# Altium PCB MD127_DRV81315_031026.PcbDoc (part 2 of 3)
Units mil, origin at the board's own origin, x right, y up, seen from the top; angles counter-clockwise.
Board outline 4400.04 x 2800.87 mil, 2 copper layers (Top Layer, Bottom Layer), stack 64.712 mil thick; 156 components, 62 nets, 376 pads, 751 vias.
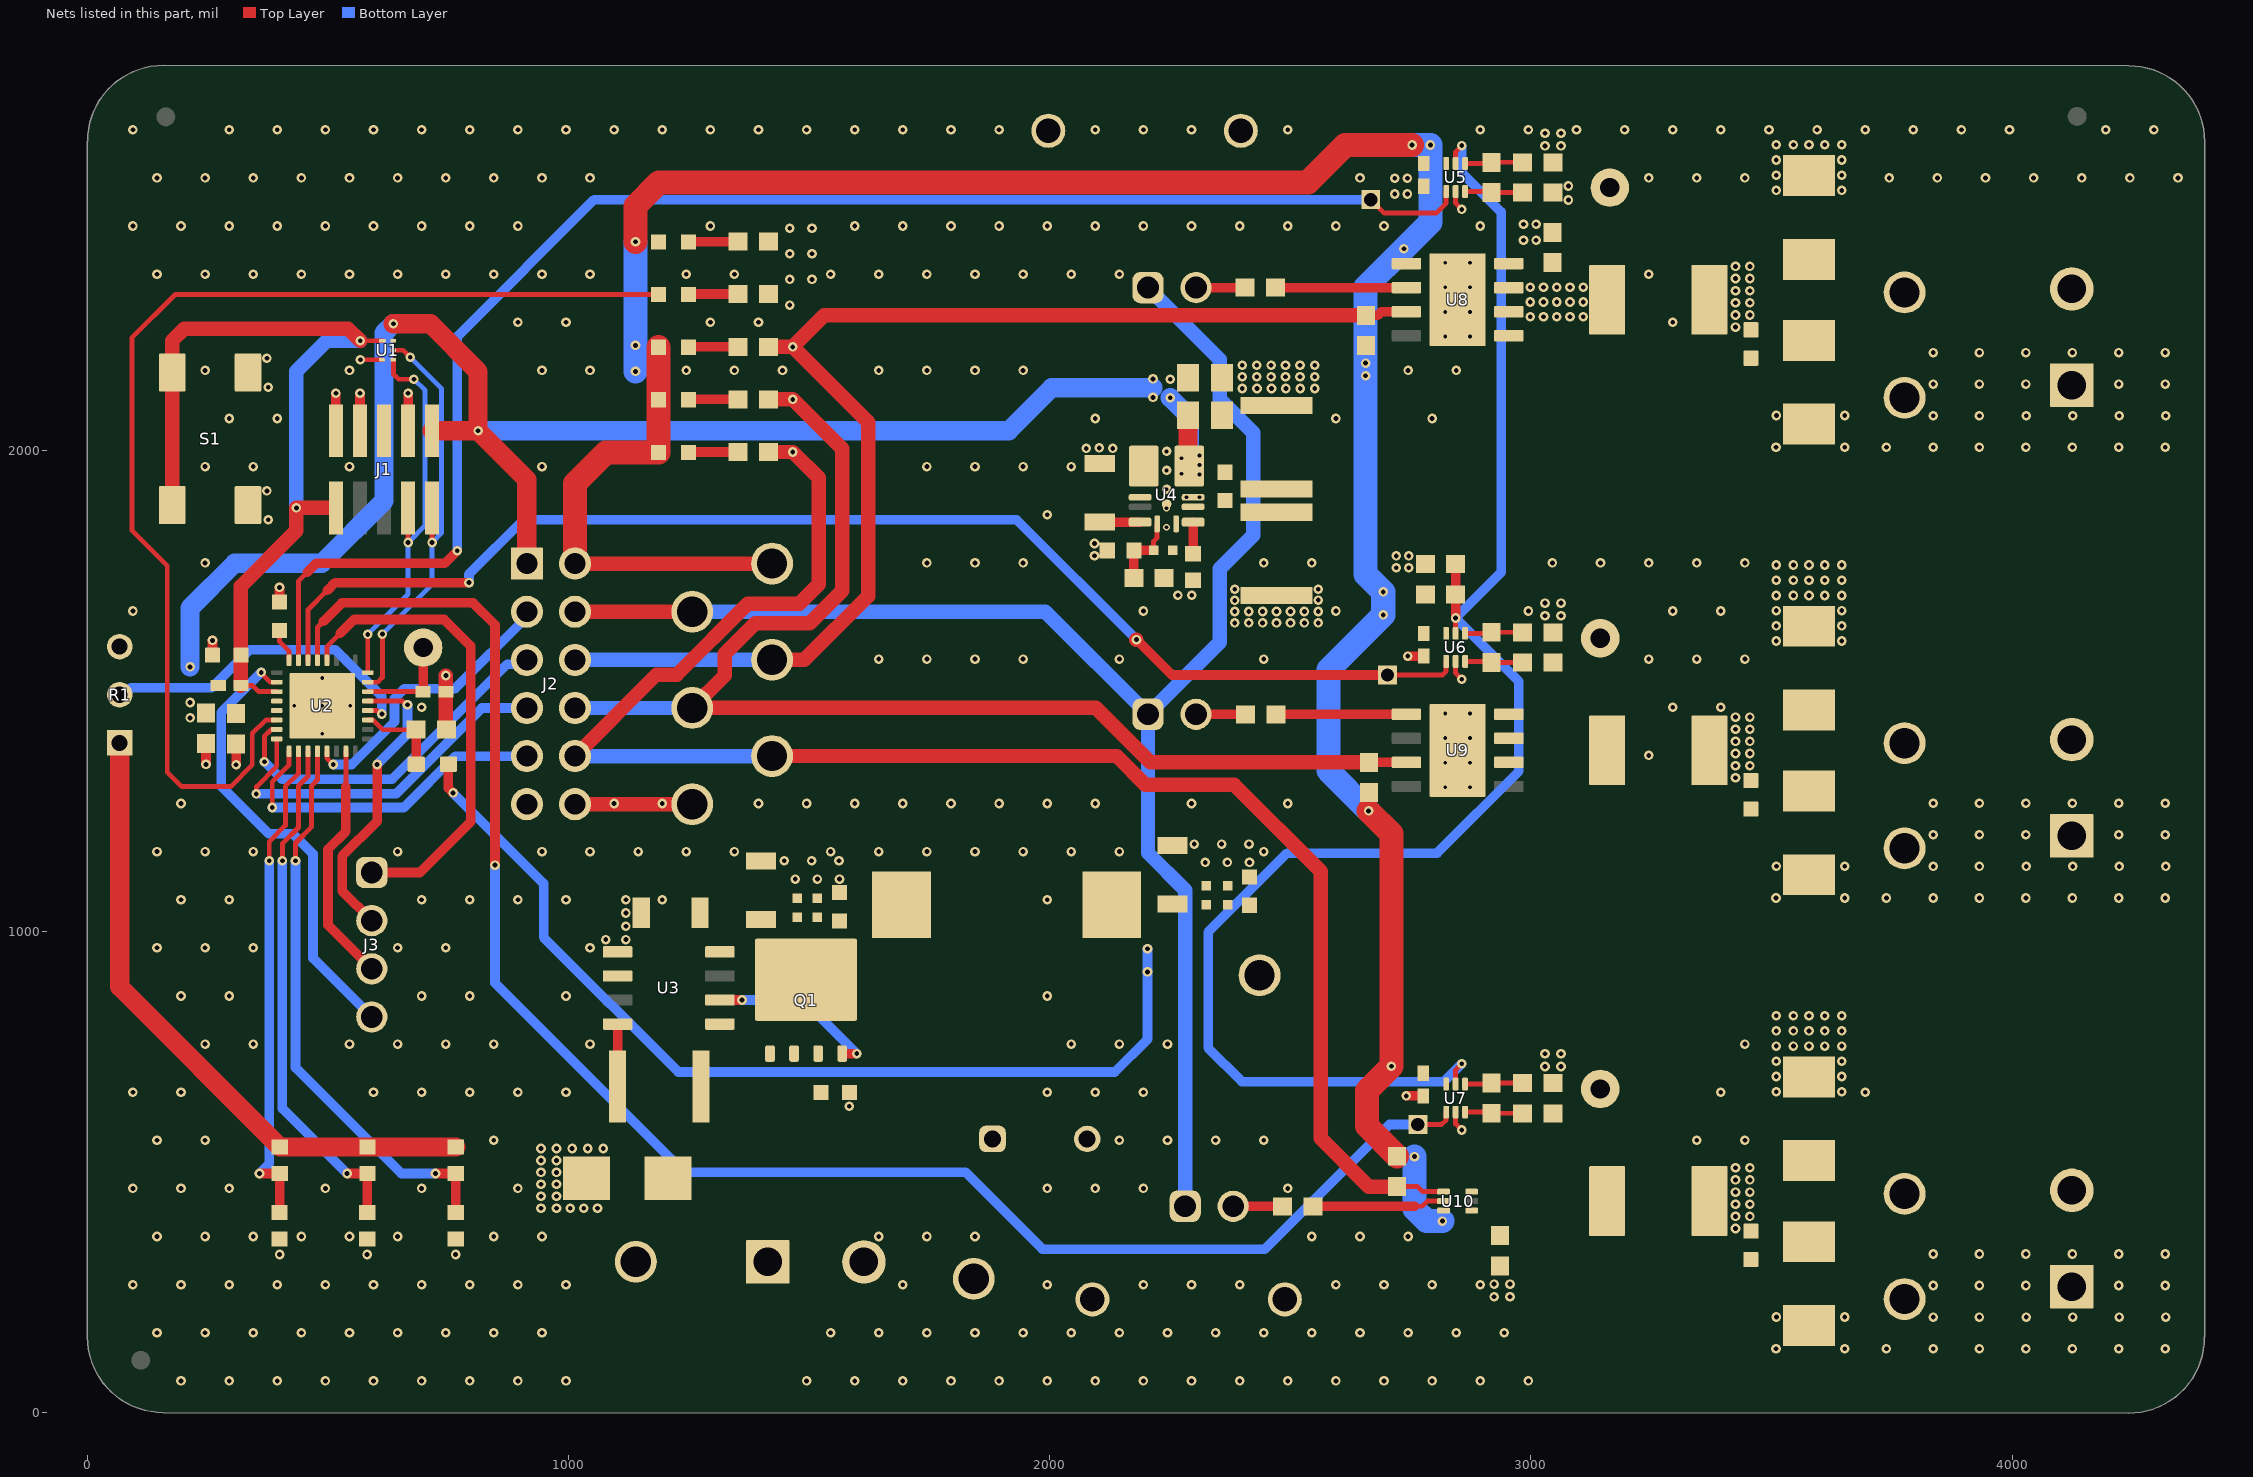
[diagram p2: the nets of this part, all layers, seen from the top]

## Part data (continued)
R1: library part CMP-0001777-2, "Trimming Potentiometer, 50K, 0.5W, TH", Manufacturer=Bourns, Supplier Part Number 1=3352T-503LF-ND
R2 R3: library part CMP-0026935-3, "RES, 47 k, 5%, 0.063 W, AEC-Q200 Grade 0, 0402", Manufacturer=Vishay-Dale, Power_W=63mW, Supplier Part Number 1=541-47KJCT-ND, TempCo="200 ppm/C", Tolerance_%=5%, Value2=0.063W, Value_Code=47k0, ValueDisplayed=47k
R4: library part CMP-0025899-5, "RES, 1.0 k, 5%, 0.1 W, 0603", Manufacturer=Yageo, Power_W=100mW, Supplier Part Number 1=311-1.0KGRCT-ND, TempCo="100 ppm/C", Tolerance_%=5%, Value2=0.1W, Value_Code=1k00, ValueDisplayed=1.0k
R5: library part CMP-0122747-1, "8 kOhms ±0.1% 0.1W, 1/10W Chip Resistor 0603 (1608 Metric) Thin Film", Digikey Part Number=13-RT0603BRE078KLCT-ND, Manufacturer=Yageo, Mouser Part Number=603-RT0603BRE078KL, Operating Temperature Range="-55°C to +155°C", Power_W=100mW, TempCo=50ppm/°C, Tolerance_%=0.1%
R6 R7 R8 R9 R10 R11 R17: library part CMP-0025886-5, "RES, 10 k, 5%, 0.1 W, 0603", Manufacturer=Yageo, Power_W=100mW, Supplier Part Number 1=311-10KGRCT-ND, TempCo="100 ppm/C", Tolerance_%=5%, Value2=0.1W, Value_Code=10k0, ValueDisplayed=10k
R12 R20 R21 R22: library part CMP-0022895-5, "RES, 1.00 k, 1%, 0.1 W, 0603", Manufacturer=Yageo, Power_W=100mW, Supplier Part Number 1=311-1.00KHRCT-ND, TempCo="100 ppm/C", Tolerance_%=1%, Value2=0.1W, Value_Code=1k00, ValueDisplayed=1.00k
R13 R14 R15 R16: library part CMP-0025912-5, "RES, 330, 5%, 0.1 W, 0603", Manufacturer=Yageo, Power_W=100mW, Supplier Part Number 1=311-330GRCT-ND, TempCo="100 ppm/C", Tolerance_%=5%, Value2=0.1W, Value_Code=330R, ValueDisplayed=330
R18: library part CMP-0022933-5, "RES, 23.2 k, 1%, 0.1 W, 0603", Manufacturer=Yageo, Power_W=100mW, Supplier Part Number 1=311-23.2KHRCT-ND, TempCo="100 ppm/C", Tolerance_%=1%, Value2=0.1W, Value_Code=23k2, ValueDisplayed=23.2k
R19: library part CMP-0025886-3, "RES, 10 k, 5%, 0.1 W, 0603", Manufacturer=Yageo, Power_W=100mW, Supplier Part Number 1=311-10KGRCT-ND, TempCo="100 ppm/C", Tolerance_%=5%, Value2=0.1W, Value_Code=10k0, ValueDisplayed=10k
R23 R24 R25: library part CMP-0023155-5, "RES, 4.99 k, 1%, 0.1 W, 0603", Manufacturer=Yageo, Power_W=100mW, Supplier Part Number 1=311-4.99KHRCT-ND, TempCo="100 ppm/C", Tolerance_%=1%, Value2=0.1W, Value_Code=4k99, ValueDisplayed=4.99k
R26 R27: library part CMP-0022902-5, "RES, 200, 1%, 0.1 W, 0603", Manufacturer=Yageo, Power_W=100mW, Supplier Part Number 1=311-200HRCT-ND, TempCo="100 ppm/C", Tolerance_%=1%, Value2=0.1W, Value_Code=200R, ValueDisplayed=200
R28 R29 R31 R32 R33 R34: library part CMP-0025874-4, "RES, 0, 5%, 0.1 W, AEC-Q200 Grade 0, 0603", Manufacturer=Panasonic, Power_W=100mW, Supplier Part Number 1=P0.0GCT-ND, TempCo="600 ppm/C", Tolerance_%=5%, Value2=0.1W, Value_Code=0000, ValueDisplayed=0
R30 R35: library part CMP-0022735-5, "RES, 100 k, 1%, 0.1 W, 0603", Manufacturer=Yageo, Power_W=100mW, Supplier Part Number 1=311-100KHRCT-ND, TempCo="100 ppm/C", Tolerance_%=1%, Value2=0.1W, Value_Code=100k
R36 R37 R38: library part CMP-0088493-1, "10 mOhms ±0.5% 2W Chip Resistor 2512 (6432 Metric) Automotive AEC-Q200, Current Sense, Moisture Resistant Metal Film", Digikey Part Number=273-PCS2512DR0100ETCT-ND, Manufacturer=Ohmite, Mouser Part Number=588-PCS2512DR0100ET, Operating Temperature Range="-55°C to +170°C", Power_W=2W, TempCo=50ppm/°C, Tolerance_%=0%
S1: library part CMP-0097347-1, "Tactile Switch SPST-NO Top Actuated Surface Mount", Coil Resistance_ohm=100mΩ, Contact Current Rating=50mA, Digikey Part Number=732-7022-1-ND, Manufacturer="Wurth Electronics", Mouser Part Number=710-430481025816, Operating Force=160gf, Operating Temperature Range="-40°C to +85°C"
SH1 SH2: library part CMP-0075110-1, "1mm Uninsulated Shorting Plug, 10.16mm spacing, TH", Manufacturer=Harwin, PartNumber=D3082-05, Supplier Part Number 1=952-1873-ND
SH1-J2 SH2-J2 SH3-J2 SH4-J2 SH5-J2 SH6-J2 SH-J5 SH-J6 SH-J7: library part CMP-0003761-2, "Shunt, 2.54mm, Gold, Black", Manufacturer="Wurth Elektronik", Supplier Part Number 1=732-2678-ND
TP1 TP11 TP12 TP13: library part CMP-0055139-2, "Test Point, Miniature, White, TH", Color=White, Manufacturer="Keystone Electronics", Supplier Part Number 1=36-5002-ND
TP2: library part CMP-0055150-1, "Test Point, Multipurpose, Orange, TH", Color=Orange, Manufacturer=Keystone, Supplier Part Number 1=36-5013-ND
TP3 TP4 TP5 TP6 TP14 TP16 TP18: library part CMP-0055149-2, "Test Point, Multipurpose, White, TH", Color=White, Manufacturer="Keystone Electronics", Supplier Part Number 1=36-5012-ND
TP7 TP9: library part CMP-0055148-2, "Test Point, Multipurpose, Black, TH", Color=Black, Manufacturer="Keystone Electronics", Supplier Part Number 1=36-5011-ND
TP8 TP10 TP15 TP17 TP19: library part CMP-0055147-2, "Test Point, Multipurpose, Red, TH", Color=Red, Manufacturer="Keystone Electronics", Supplier Part Number 1=36-5010-ND
U1: library part CMP-0043115-2, "ESD-Protection Array for High-Speed Data Interfaces, 4 Channels, -40 to +85 degC, 6-pin SON (DRY), Green (RoHS & no Sb/Br)", Breakdown Voltage(Min)(V)=6, IO Capacitance(Typ)(pF)=1.6, IO Leakage Current(nA)=1, Manufacturer="Texas Instruments"
U2: library part CMP-0093963-1, "Mixed-Signal Microcontrollers with CAN-FD Interface, VQFN32", Frequency_Fixed=80MHz, Manufacturer="Texas Instruments", Max Supply Voltage=3.6V, Min Supply Voltage=1.62V, Operating Temperature Range="-40°C to +125°C"
U3: library part CMP-0125797-1, Manufacturer="Texas Instruments", Operating Temperature Range=to, Part Number=LM74700D-Q1
U4: library part CMP-0094617-1, "3-V to 65-V Input, 1-V to 13-V Output, 600-mA Synchronous Buck Converter Power Module in a HotRod QFN Package", Manufacturer="Texas Instruments", Max Supply Voltage=65V, Min Supply Voltage=3.6V, Nominal Supply Current=17-18uA, Operating Temperature Range="-40°C to +125°C", Output Voltage=1-13V, Switching Frequency=200-2200kHz
U5 U6 U7: library part CMP-0085242-1, "Bidirectional, Precision Low- and High-Side Voltage Output, Current-Sense Amplifier, DRL0006A (SOT-5X3-6)", Alternate Manufacturer="Texas Instruments", Alternate PartNumber=INA185A2IDRLT
U8: library part CMP-0127675-1, "Protected Low-Side Switch, HSOIC8", Manufacturer="Texas Instruments", Max Supply Voltage=5.5V, Min Supply Voltage=3V, Nominal Supply Current=40uA, Operating Temperature Range="-40°C to +150°C"
U9: library part CMP-0127704-1, "Protected Low-Side Switch, HSOIC8", Manufacturer="Texas Instruments", Max Supply Voltage=5.5V, Min Supply Voltage=3V, Nominal Supply Current=40uA, Operating Temperature Range="-40°C to +150°C"
U10: library part CMP-0127676-1, "Protected Low-Side Switch, SOT563", Manufacturer="Texas Instruments", Max Supply Voltage=5.5V, Min Supply Voltage=3V, Nominal Supply Current=40uA, Operating Temperature Range="-40°C to +150°C"
ZZ1: library part CMP-0003616-3
ZZ2: library part CMP-0077236-1
ZZ3: library part CMP-0077237-1
ZZ4: library part CMP-0077238-1

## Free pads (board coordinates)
  rect 39.37x39.37 hole 27.56: 7(2667,2521) 7(2702,1533) 7(2765,599)

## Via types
v1: diameter 20, hole 10, Top Layer to Bottom Layer, tented both sides, 718 vias
v2: diameter 19.68, hole 7.87, Top Layer to Bottom Layer, tented both sides, 29 vias
v3: diameter 14, hole 8, Top Layer to Bottom Layer, tented both sides, 4 vias

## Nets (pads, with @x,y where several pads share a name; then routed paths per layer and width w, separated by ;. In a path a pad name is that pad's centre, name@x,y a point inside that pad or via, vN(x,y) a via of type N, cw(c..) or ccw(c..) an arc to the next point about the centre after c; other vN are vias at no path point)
3V3: C24.2 C25.2 C26.2 D1.2 D3.2 D4.2 D5.2 J2.2 R23.1 R24.1 R25.1 R27.2 TP2.1 U5.6 U6.6 U7.6 U8.1 U10.3 | length 5541.6
  Top Layer w30: J2.2@1013.3,1764.56 1422.78,1764.56 TP2.1@1422.91,1764.69
  Top Layer w50: J2.2@1013.3,1764.56 1013.3,1931.3 1077.77,1995.77 D5.2@1186.51,1995.77 D4.2@1186.51,2105 D3.2@1186.51,2214.23 ; v1(1139,2433.35) 1139,2507.82 1188.18,2557 2536.33,2557 2613.97,2634.63 v1(2753,2634.63) ; v1(2662.59,1250.67) 2710,1203.26 v1(2710,720) 2659,669 2659,595.53 R25.1@2721.62,532.91
  Bottom Layer w50: v1(1139,2164) v1(1139,2218) v1(1139,2433.35) ; v1(2662.59,1250.67) 2579,1334.26 2579,1544 v1(2693,1658) v1(2693,1705.81) 2656.37,1742.44 v1(2656.37,2155) v1(2656.37,2181.25) 2656.37,2339.37 v1(2736,2419) 2791,2474 v1(2791,2634.63) v1(2753,2634.63) ; v1(2757.87,532.28) 2757.87,423.64 2783.27,398.23 v1(2815.98,398.23)
A0_3_ADC0_AUX: J3.1 U2.28 | length 987.9
  Top Layer w10: U2.28@497.84,1563.49 497.84,1592.09 525.72,1619.96
  Top Layer w20: 525.72,1619.96 554.21,1648.46 741.54,1648.46 796.3,1593.7 796.3,1227.82 691,1122.52 J3.1@591,1122.52
A1_2_ADC1_AUX: J3.2 U2.21 | length 616.1
  Top Layer w10: U2.21@582.49,1478.84 654.74,1478.84 662.44,1471.15 v1(665.14,1471.15)
  Top Layer w20: J3.2@591,1022.52 529.57,1083.95 529.57,1156.57 602,1229 v1(602,1347)
  Bottom Layer w20: v1(602,1347) 665.14,1410.14 v1(665.14,1471.15)
BSL_INVOKE: R3.2 TP1.1 U2.22 | length 206.7
  Top Layer w10: U2.22@582.49,1498.53 R3.2@697.75,1498.53
  Top Layer w20: R3.2@697.75,1498.53 TP1.1@697.75,1590
BUCK_3V3: C3.1 C4.1 C13.1 C14.1 C16.2 J1.1 J2.1 R1.1 R2.2 R6.1 R7.1 R8.1 R18.2 R19.2 U1.6 U2.4 U4.4 | length 4795.6
  Top Layer w40: R1.1@67,1392.09 67,885.06 R6.1@399.78,552.28 R7.1@581.76,552.28 R8.1@765.55,552.28 ; v1(635.81,2263) 713,2263 812,2164 v1(812,2040.6) ; J1.1@716.46,2040.6 v1(812,2040.6) ; J2.1@913.3,1764.56 913.3,1939.3 v1(812,2040.6) ; C14.1@2287.28,2072.53 2287.28,1970.04 U4.4@2290,1967.32
  Bottom Layer w40: v1(213.44,1550) 213.44,1672.44 306.22,1765.22 487.1,1765.22 616.46,1894.57 616.46,2243.64 v1(635.81,2263) ; v1(812,2040.6) 1914.6,2040.6 2004,2130 2214.62,2130 ; v1(2250.54,2109.14) 2290,2069.68 2290,1967.32
  other v1: 213.44,1444 213.44,1475.91 2266.18,1698.64 2295.07,1698.64 2214.62,2110.02 2214.62,2148.42 2250.54,2147.77
  other v2: 2310.87,1949.61 2273.46,1951.18 2310.87,1969.29 2273.46,1983.46 2310.87,1988.98
DEV_ID1: R6.2 R9.1 U2.10 | length 1034.2
  Top Layer w10: v1(378.01,1147.18) 378.01,1187.01 411.55,1220.55 411.55,1301.79 438.79,1329.02 U2.10@438.79,1374.51
  Top Layer w20: v1(357.76,497.16) R6.2@399.78,497.16 399.78,416.28 R9.1@399.48,415.98
  Bottom Layer w20: v1(357.76,497.16) 378.01,517.42 v1(378.01,1147.18)
DEV_ID2: R7.2 R10.1 U2.11 | length 1078.5
  Top Layer w10: v1(405.13,1147.18) 405.13,1182.67 438.67,1216.21 438.67,1302.52 458.47,1322.32 U2.11@458.47,1374.51
  Top Layer w20: v1(539.73,497.16) R7.2@581.76,497.16 581.76,416.14 R10.1@581.6,415.98
  Bottom Layer w20: v1(405.13,1147.18) 405.13,631.77 v1(539.73,497.16)
DEV_ID3: R8.2 R11.1 U2.12 | length 1181.8
  Top Layer w10: v1(432.46,1147.18) 432.46,1183.97 466,1217.51 466,1303 478.16,1315.16 U2.12@478.16,1374.51
  Top Layer w20: v1(723.52,497.16) R8.2@765.55,497.16 R11.1@765.55,415.98
  Bottom Layer w20: v1(432.46,1147.18) 432.46,717.03 652.33,497.16 v1(723.52,497.16)
GND: C1.1 C2.2 C3.2 C4.2 C5.1 C6.1 C7.1 C8.1 C9.1 C11.1 C12.2 C13.2 C14.2 C15.1 C17.1 C18.1 C19.1 C20.1 C21.1 C22.1 C23.1 C24.1 C25.1 C26.1 C30.1 C31.1 C32.1 D6.2 D7.1 D8.1 D9.1 J1.3 J1.5 J1.7 J1.9 J2.11 J2.12 J4.2 R1.3 R3.1 R4.1 R9.2 R10.2 R11.2 R12.1 R13.1 R17.1 R26.1 R28.1 R30.1 R31.1 R33.1 R35.1 R36.1 R37.1 R38.1 S1.3 S1.4 SH1.1 SH1.2 SH2.1 SH2.2 TP7.1 TP9.1 U1.3 U2.5 U2.33 U3.1 U4.10 U4.11 U5.2 U6.2 U7.2 U8.9 | length 978.8
  Top Layer w10: v1(567.33,2188.31) U1.3@612.19,2188.31 ; U7.2@2843.37,624.64 2843.37,600.18 v1(2856,587.55) ; U6.2@2843.37,1561.27 2843.37,1536.81 v1(2856,1524.18) ; U5.2@2843.37,2537.91 2843.37,2513.45 v1(2856,2500.82)
  Top Layer w20: v1(246.51,1347.4) C3.2@246.51,1390.71 ; C2.2@260.01,1574.33 v1(260.01,1605) ; v1(309,1346.7) C4.2@309,1390.01 ; C1.1@399.1,1684.52 v1(399.1,1715.19) ; J1.9@516.46,2040.6 v1(516.46,2118.55) ; J1.7@566.45,2040.6 v1(566.45,2118.55) ; J1.3@666.45,2040.6 v1(666.45,2118.55) ; v1(2741,658.3) C26.1@2775.95,658.3 ; v1(2744,1572.3) C25.1@2777.36,1572.3
  Top Layer w30: v1(744.99,1531.99) R3.1@744.99,1498.53 744.99,1420.81 R4.1@746.33,1419.47 ; J2.12@1013.3,1264.56 1256.9,1264.56 TP7.1@1257.04,1264.69
  other v1: 194.61,66.09 294.61,66.09 394.61,66.09 494.61,66.09 594.61,66.09 694.61,66.09 794.61,66.09 894.61,66.09 994.61,66.09 1494.61,66.09 1594.61,66.09 1694.61,66.09 1794.61,66.09 1894.61,66.09 1994.61,66.09 2094.61,66.09 2194.61,66.09 2294.61,66.09 2394.61,66.09 2494.61,66.09 2594.61,66.09 2694.61,66.09 2794.61,66.09 2894.61,66.09 2994.61,66.09 144.61,166.09 244.61,166.09 344.61,166.09 444.61,166.09 544.61,166.09 644.61,166.09 744.61,166.09 844.61,166.09 944.61,166.09 1544.61,166.09 1644.61,166.09 1744.61,166.09 1844.61,166.09 1944.61,166.09 2044.61,166.09 2144.61,166.09 2244.61,166.09 2344.61,166.09 2444.61,166.09 2544.61,166.09 2644.61,166.09 2744.61,166.09 2844.61,166.09 2944.61,166.09 2923.33,241 2956.35,241 94.61,266.09 194.61,266.09 294.61,266.09 394.61,266.09 494.61,266.09 594.61,266.09 694.61,266.09 794.61,266.09 894.61,266.09 994.61,266.09 1694.61,266.09 1994.61,266.09 2194.61,266.09 2294.61,266.09 2394.61,266.09 2594.61,266.09 2694.61,266.09 2794.61,266.09 2894.61,266.09 2923.33,267.26 2956.35,267.26 399.4,328.75 581.38,328.75 765.17,328.75 144.61,366.09 244.61,366.09 344.61,366.09 444.61,366.09 544.61,366.09 644.61,366.09 844.61,366.09 944.61,366.09 1644.61,366.09 1744.61,366.09 1844.61,366.09 2544.61,366.09 2644.61,366.09 2744.61,366.09 3425,382.75 3425,408 3455,408 942.67,425 975,425 1003.33,425 1031.67,425 1060,425 3425,433.25 3455,433.25 942.67,449.8 975,449.8 3425,458.5 3455,458.5 94.61,466.09 194.61,466.09 294.61,466.09 494.61,466.09 694.61,466.09 894.61,466.09 1994.61,466.09 2094.61,466.09 2194.61,466.09 2494.61,466.09 942.67,474.6 975,474.6 3425,483.75 3455,483.75 942.67,499.4 975,499.4 3425,509 3455,509 942.67,524.2 975,524.2 942.67,549 975,549 1007.33,549 1039.67,549 1072,549 144.61,566.09 244.61,566.09 844.61,566.09 2144.61,566.09 2244.61,566.09 2344.61,566.09 2444.61,566.09 3344.61,566.09 3444.61,566.09 1583.24,636.99 94.61,666.09 194.61,666.09 594.61,666.09 694.61,666.09 794.61,666.09 894.61,666.09 994.61,666.09 1994.61,666.09 2094.61,666.09 2194.61,666.09 3394.61,666.09 3694.61,666.09 3509.77,667 3646,667 3509.77,698.6 3646,698.6 3029.3,719.52 3062.32,719.52 3509.77,730.2 3646,730.2 3029.3,745.78 3062.32,745.78 3509.77,761.8 3545.33,761.8 3577.88,761.8 3610.44,761.8 3646,761.8 244.61,766.09 344.61,766.09 544.61,766.09 644.61,766.09 744.61,766.09 844.61,766.09 1044.61,766.09 2044.61,766.09 2144.61,766.09 2244.61,766.09 3444.61,766.09 3509.77,793.4 3545.33,793.4 3577.88,793.4 3610.44,793.4 3646,793.4 3509.77,825 3545.33,825 3577.88,825 3610.44,825 3646,825 194.61,866.09 294.61,866.09 694.61,866.09 794.61,866.09 994.61,866.09 1994.61,866.09 144.61,966.09 244.61,966.09 344.61,966.09 644.61,966.09 744.61,966.09 1044.61,966.09 1077.4,983.26 1119,983.26 1119,1010.84 1119,1038.42 194.61,1066.09 294.61,1066.09 694.61,1066.09 794.61,1066.09 894.61,1066.09 994.61,1066.09 1119,1066 1194.61,1066.09 1994.61,1066.09 1471,1109 1517,1109 1563,1109 2323.07,1143.66 2369.07,1143.66 2415.07,1143.66 1448,1147 1505,1147 1562,1147 144.61,1166.09 244.61,1166.09 344.61,1166.09 644.61,1166.09 944.61,1166.09 1044.61,1166.09 1144.61,1166.09 1244.61,1166.09 1344.61,1166.09 1544.61,1166.09 1644.61,1166.09 1744.61,1166.09 1844.61,1166.09 1944.61,1166.09 2044.61,1166.09 2144.61,1166.09 2444.61,1166.09 2300.07,1181.66 2357.07,1181.66 2414.07,1181.66 194.61,1266.09 1094.61,1266.09 1194.61,1266.09 1394.61,1266.09 1494.61,1266.09 1594.61,1266.09 1694.61,1266.09 1794.61,1266.09 1894.61,1266.09 1994.61,1266.09 2094.61,1266.09 2294.61,1266.09 2494.61,1266.09 3425,1319.38 3425,1344.63 3455,1344.63 3244.61,1366.09 3425,1369.88 3455,1369.88 3425,1395.13 3455,1395.13 3425,1420.38 3455,1420.38 3425,1445.63 3455,1445.63 694.61,1466.09 3294.61,1466.09 3394.61,1466.09 1644.61,1566.09 1744.61,1566.09 1844.61,1566.09 1944.61,1566.09 2144.61,1566.09 2444.61,1566.09 3244.61,1566.09 3344.61,1566.09 3444.61,1566.09 3509.77,1603.63 3646,1603.63 3509.77,1635.23 3646,1635.23 2384.48,1641.35 2413.41,1641.35 2442.34,1641.35 2471.27,1641.35 2500.2,1641.35 2529.13,1641.35 2558.06,1641.35 3029.31,1656.15 3062.32,1656.15 2384.48,1665 2413.41,1665 2442.34,1665 2471.27,1665 2500.2,1665 2529.13,1665 2558.06,1665 94.61,1666.09 2194.61,1666.09 2594.61,1666.09 2994.61,1666.09 3294.61,1666.09 3394.61,1666.09 3509.77,1666.83 3646,1666.83 3029.31,1682.41 3062.32,1682.41 2384.48,1688.14 2558.06,1688.65 3509.77,1698.43 3545.33,1698.43 3577.88,1698.43 3610.44,1698.43 3646,1698.43 2384.48,1711.28 2558.06,1711.28 3509.77,1730.03 3545.33,1730.03 3577.88,1730.03 3610.44,1730.03 3646,1730.03 2719.87,1755.87 2746.13,1755.87 3509.77,1761.63 3545.33,1761.63 3577.88,1761.63 3610.44,1761.63 3646,1761.63 244.61,1766.09 1744.61,1766.09 1844.61,1766.09 1944.61,1766.09 2444.61,1766.09 2544.61,1766.09 3044.61,1766.09 3144.61,1766.09 3244.61,1766.09 3344.61,1766.09 3444.61,1766.09 2092.99,1781.08 2719.87,1780.67 2746.13,1780.67 2092.99,1806.4 375.87,1855.68 1994.61,1866.09 373.01,1915.79 244.61,1966.09 344.61,1966.09 544.61,1966.09 944.61,1966.09 1744.61,1966.09 1844.61,1966.09 1944.61,1966.09 2044.61,1966.09 2076,2004 2131,2004 2103,2005 294.61,2066.09 394.61,2066.09 2094.61,2066.09 2594.61,2066.09 2794.61,2066.09 2400,2128.59 2430.67,2128.59 2460.67,2128.59 2490.67,2128.59 2520.67,2128.59 2550.67,2128.59 375.87,2131.27 2400,2152.79 2430,2152.79 2460,2152.79 2490,2152.79 2520,2152.79 2550.67,2152.79 244.61,2166.09 544.61,2166.09 944.61,2166.09 1044.61,2166.09 1244.61,2166.09 1344.61,2166.09 1444.61,2166.09 1644.61,2166.09 1744.61,2166.09 1844.61,2166.09 1944.61,2166.09 2744.61,2166.09 2844.61,2166.09 2400,2177 2430,2177 2460,2177 2490,2177 2520,2177 2550.67,2177 373.01,2191.38 3425,2256.01 894.61,2266.09 994.61,2266.09 1294.61,2266.09 1394.61,2266.09 3294.61,2266.09 3425,2281.26 3455,2281.26 1459.77,2301.9 3425,2306.51 3455,2306.51 3425,2331.76 3455,2331.76 1459.77,2355.17 1505.78,2355.17 3425,2357.01 3455,2357.01 144.61,2366.09 244.61,2366.09 344.61,2366.09 444.61,2366.09 544.61,2366.09 644.61,2366.09 744.61,2366.09 844.61,2366.09 944.61,2366.09 1044.61,2366.09 1244.61,2366.09 1344.61,2366.09 1544.61,2366.09 1644.61,2366.09 1744.61,2366.09 1844.61,2366.09 1944.61,2366.09 2044.61,2366.09 2144.61,2366.09 3244.61,2366.09 3425,2382.26 3455,2382.26 1459.77,2408.44 1505.78,2408.44 2984.5,2436.64 3010.75,2436.64 1459.77,2461.71 1505.78,2461.71 94.61,2466.09 194.61,2466.09 294.61,2466.09 394.61,2466.09 494.61,2466.09 594.61,2466.09 694.61,2466.09 794.61,2466.09 894.61,2466.09 1294.61,2466.09 1594.61,2466.09 1694.61,2466.09 1794.61,2466.09 1894.61,2466.09 1994.61,2466.09 2094.61,2466.09 2194.61,2466.09 2294.61,2466.09 2394.61,2466.09 2494.61,2466.09 2594.61,2466.09 2694.61,2466.09 2894.61,2466.09 2984.5,2469.66 3010.75,2469.66 2716.86,2532.58 2743.11,2532.58 3509.77,2540.26 3646,2540.26 144.61,2566.09 244.61,2566.09 344.61,2566.09 444.61,2566.09 544.61,2566.09 644.61,2566.09 744.61,2566.09 844.61,2566.09 944.61,2566.09 1044.61,2566.09 2644.61,2566.09 2716.86,2565.6 2743.11,2565.6 3244.61,2566.09 3344.61,2566.09 3444.61,2566.09 3744.61,2566.09 3844.61,2566.09 3944.61,2566.09 4044.61,2566.09 4144.61,2566.09 4244.61,2566.09 4344.61,2566.09 3509.77,2571.86 3646,2571.86 3509.77,2603.46 3646,2603.46 3029.31,2632.78 3062.32,2632.78 3509.77,2635.06 3545.33,2635.06 3577.88,2635.06 3610.44,2635.06 3646,2635.06 3029.31,2659.04 3062.32,2659.04 94.61,2666.09 294.61,2666.09 394.61,2666.09 494.61,2666.09 594.61,2666.09 694.61,2666.09 794.61,2666.09 894.61,2666.09 994.61,2666.09 1094.61,2666.09 1194.61,2666.09 1294.61,2666.09 1394.61,2666.09 1494.61,2666.09 1594.61,2666.09 1694.61,2666.09 1794.61,2666.09 1894.61,2666.09 2094.61,2666.09 2194.61,2666.09 2294.61,2666.09 2494.61,2666.09 2894.61,2666.09 2994.61,2666.09 3094.61,2666.09 3194.61,2666.09 3294.61,2666.09 3394.61,2666.09 3494.61,2666.09 3594.61,2666.09 3694.61,2666.09 3794.61,2666.09 3894.61,2666.09 3994.61,2666.09 4194.61,2666.09 4294.61,2666.09
  other v2: 488,1410.93 429.93,1469 488,1469 546.07,1469 488,1527.07 2242.76,1918.9 2242.76,1958.27 2242.76,1997.64 2821.91,2236.34 2873.09,2236.34 2821.91,2287.52 2873.09,2287.52 2821.91,2338.7 2873.09,2338.7 2821.91,2389.88 2873.09,2389.88
  other v3: 2242.76,1840.16 2242.76,1879.53
IN: J2.4 J5.1 J6.1 J7.1 TP3.1 | length 3401.6
  Top Layer w30: J2.4@1013.3,1664.56 1256.9,1664.56 TP3.1@1257.04,1664.69
  Bottom Layer w30: TP3.1@1257.04,1664.69 1990.9,1664.69 J6.1@2204.12,1451.48 ; J5.1@2204.12,2338.11 2353.48,2188.74 2353.48,2106.22 2423,2036.7 2423,1823.55 2353.48,1754.03 2353.48,1600.85 J6.1@2204.12,1451.48 ; J7.1@2281.28,429 2281.28,1086.11 2204.12,1163.28 J6.1@2204.12,1451.48
IN_U1: R20.2 U8.2 | length 272.3
  Top Layer w20: R20.2@2468.95,2338.11 U8.2@2741.2,2338.11
IN_U2: R21.2 U9.1 | length 271.4
  Top Layer w20: R21.2@2469.84,1451.48 U9.1@2741.2,1451.48
IN_U3: R22.2 U10.2 | length 275.9
  Top Layer w10: 2758.31,429 2774,429 2784.84,439.84 U10.2@2818.37,439.84
  Top Layer w20: R22.2@2547,429 2758.31,429
INA_REF: R26.2 R27.1 U5.5 U6.5 U7.5 | length 3258.4
  Top Layer w10: U7.5@2843.37,682.91 2843.37,712.37 v1(2856,725) ; U6.5@2843.37,1619.54 v1(2843.37,1651.63) ; U5.5@2843.37,2596.17 2843.37,2620.63 v1(2856,2633.26)
  Top Layer w20: v1(2843.37,1651.63) R27.1@2843.37,1700 R26.2@2843.37,1764
  Bottom Layer w20: v1(2856,725) 2818.93,687.93 2399.31,687.93 2329.17,758.07 2329.17,998.79 2493.38,1163 2805,1163 2975.01,1333.01 2975.01,1519.99 v1(2843.37,1651.63) 2938.16,1746.43 2938.16,2495.59 2856,2577.75 v1(2856,2633.26)
MCU_STATUS: D2.2 U2.6 | length 2399.7
  Top Layer w10: U2.6@393.51,1439.47 370.47,1439.47 342.57,1411.57 342.57,1346.27 297.54,1301.24 195.95,1301.24 166,1331.19 166,1760 92.5,1833.5 92.5,2233.5 183.12,2324.12 D2.2@1186.51,2324.12
NetC1_2: C1.2 U2.32 | length 70.3
  Top Layer w10: C1.2@399.1,1625.47 399.1,1602.9 419.1,1582.9 U2.32@419.1,1563.49
NetC10_1: C10.1 U3.4 | length 129.3
  Top Layer w20: C10.1@1101.85,678.32 U3.4@1101.85,807.65
NetC15_2: C15.2 U4.8 | length 83.7
  Top Layer w20: C15.2@2103.93,1850.71 U4.8@2187.64,1850.71
NetC16_1: C16.1 R17.2 R18.1 U4.9 | length 156.5
  Top Layer w10: C16.1@2215.87,1792.13 2215.87,1810.87 2223.07,1818.07 U4.9@2223.07,1847.24
  Top Layer w20: R18.1@2174.7,1734.88 R17.2@2174.7,1792.13 C16.1@2215.87,1792.13
NetD1_1: D1.1 R12.2 | length 102.9
  Top Layer w20: D1.1@1249.5,2432.69 1250.3,2433.49 R12.2@1352.12,2433.49
NetD2_1: D2.1 R13.2 | length 102.9
  Top Layer w20: D2.1@1249.5,2324.12 1250.3,2324.91 R13.2@1352.12,2324.91
NetD3_1: D3.1 R14.2 | length 102.9
  Top Layer w20: D3.1@1249.5,2214.23 1250.3,2215.03 R14.2@1352.12,2215.03
NetD4_1: D4.1 R15.2 | length 102.9
  Top Layer w20: D4.1@1249.5,2105 1250.3,2105.8 R15.2@1352.12,2105.8
NetD5_1: D5.1 R16.2 | length 102.9
  Top Layer w20: D5.1@1249.5,1995.77 1250.3,1996.56 R16.2@1352.12,1996.56
NetJ5_2: J5.2 R20.1 | length 101.8
  Top Layer w20: J5.2@2304.12,2338.11 R20.1@2405.95,2338.11
NetJ6_2: J6.2 R21.1 | length 102.7
  Top Layer w20: J6.2@2304.12,1451.48 R21.1@2406.84,1451.48
NetJ7_2: J7.2 R22.1 | length 102.7
  Top Layer w20: J7.2@2381.28,429 R22.1@2484.01,429
NetQ1_4: Q1.4 U3.6 | length 360.7
  Top Layer w20: U3.6@1314.45,857.65 v1(1360.35,857.65) ; Q1.4@1568.58,746.21 v1(1598.79,746.21)
  Bottom Layer w20: v1(1360.35,857.65) 1487.35,857.65 v1(1598.79,746.21)
NetR19_1: R19.1 U4.1 | length 65.6
  Top Layer w20: R19.1@2297.87,1785.08 U4.1@2297.87,1850.71
NetU4_5: U4.5 U4.6
nRST: C2.1 J1.10 R2.1 S1.1 S1.2 U1.1 U2.3 | length 1821.1
  Top Layer w10: R2.1@319.07,1511.18 343.45,1511.18 356.1,1498.53 U2.3@393.51,1498.53 ; v1(566.9,2227.69) U1.1@613.17,2227.69
  Top Layer w30: S1.1@176.26,1886.2 S1.2@176.26,2161.8 176.26,2228.15 201.11,2253 541.59,2253 v1(566.9,2227.69) ; R2.1@319.07,1511.18 C2.1@319.07,1574.33 319.07,1717.63 434.36,1832.92 v1(434.36,1880.36) J1.10@516.46,1880.36
  Bottom Layer w30: v1(434.36,1880.36) 434.36,2164.36 497.69,2227.69 v1(566.9,2227.69)
OUT_U1: C30.2 D7.2 D10.2 J8.2 R30.2 TP14.1 U8.5 U8.8
OUT_U2: C31.2 D8.2 D11.2 J9.2 TP16.1 U9.9
  other v2: 2821.91,1299.7 2873.09,1299.7 2821.91,1350.89 2873.09,1350.89 2821.91,1402.07 2873.09,1402.07 2821.91,1453.25 2873.09,1453.25
OUT_U3: C32.2 D9.2 D12.2 J10.2 R35.2 TP18.1 U10.4
PA1_GPIO_AUX: J3.4 U2.2 | length 951.1
  Top Layer w10: v1(361.12,1538.57) 361.12,1536.96 379.86,1518.21 U2.2@393.51,1518.21
  Bottom Layer w20: v1(361.12,1538.57) 278,1455.46 278,1302 377.04,1202.96 426.85,1202.96 468.78,1161.03 468.78,944.74 J3.4@591,822.52
PI_IN: C5.2 C6.2 C7.2 C8.2 C9.2 C12.1 L1.1 Q1.5 Q1.6 Q1.7 Q1.8 Q1.9@1493.58,899.75 U3.8
POT_IN: R1.2 U2.20 | length 693.3
  Top Layer w10: U2.20@582.49,1459.16 602.14,1459.16 609.29,1452 v1(612,1452)
  Bottom Layer w20: R1.2@67,1492.09 75.97,1492.09 90.35,1506.46 258.22,1506.46 337.69,1585.93 514.77,1585.93 612,1488.7 v1(612,1452)
PWM_IN1: J2.3 U2.13 | length 601.2
  Top Layer w10: U2.13@497.84,1374.51 497.84,1360.16 v1(511,1347)
  Bottom Layer w20: v1(511,1347) 549.38,1347 638.31,1435.93 638.31,1484.18 658.85,1504.71 763.91,1504.71 913.3,1654.1 J2.3@913.3,1664.56
PWM_IN2_AUX: J3.3 U2.15 | length 505.2
  Top Layer w10: 537.21,1301.23 U2.15@537.21,1374.51
  Top Layer w20: 537.21,1301.23 537.21,1208.21 499.93,1170.93 499.93,1013.59 J3.3@591,922.52
SRC_U1: R29.1 R36.2 TP11.1 U8.6 U8.7
  other v1: 2998.5,2277.46 3026.04,2277.46 3053.58,2277.46 3081.11,2277.46 3108.65,2277.46 2998.5,2308.23 3026.04,2308.23 3053.58,2308.23 3081.11,2308.23 3108.65,2308.23 2998.5,2339 3026.04,2339 3053.58,2339 3081.11,2339 3108.65,2339 3077.77,2520.29 3077.77,2549.31
SRC_U1_ADDA_MCU: pad.7@2667,2521 U2.31 U5.1 | length 3183.5
  Top Layer w10: U2.31@438.79,1563.49 438.79,1728.79 457,1747 ; pad.7@2667,2521 2694.99,2493.01 2802.88,2493.01 2823.69,2513.82 U5.1@2823.69,2537.91
  Top Layer w20: 457,1747 475.22,1765.22 742.61,1765.22 v1(768.73,1791.34)
  Bottom Layer w20: v1(768.73,1791.34) 768.73,2236.73 1053,2521 pad.7@2667,2521
SRC_U1_IN_N: C27.2 R28.2 U5.4 | length 120.6
  Top Layer w10: U5.4@2863.06,2596.17 2915.53,2596.17 C27.2@2917.89,2598.54 R28.2@2982.67,2598.54
SRC_U1_IN_P: C27.1 R29.2 U5.3 | length 120.6
  Top Layer w10: U5.3@2863.06,2537.91 2915.53,2537.91 C27.1@2917.89,2535.54 R29.2@2982.67,2535.54
SRC_U2: R32.1 R37.2 TP12.1 U9.6 U9.7 U9.8
SRC_U2_DDA_MCU: pad.7@2702,1533 U2.30 U6.1 | length 2715.7
  Top Layer w10: U2.30@458.47,1563.49 458.47,1668.85 498.63,1709.01 ; pad.7@2702,1533 2815.92,1533 2823.69,1540.77 U6.1@2823.69,1561.27
  Top Layer w20: 498.63,1709.01 514.74,1725.12 v1(793.12,1725.12) ; v1(2180.15,1606.74) 2253.89,1533 pad.7@2702,1533
  Bottom Layer w20: v1(793.12,1725.12) 793.12,1742.68 906.21,1855.77 1931.12,1855.77 v1(2180.15,1606.74)
SRC_U2_IN_N: C28.2 R31.2 U6.4 | length 120.6
  Top Layer w10: U6.4@2863.06,1619.54 2915.53,1619.54 C28.2@2917.89,1621.9 R31.2@2982.66,1621.9
SRC_U2_IN_P: C28.1 R32.2 U6.3 | length 120.6
  Top Layer w10: U6.3@2863.06,1561.27 2915.53,1561.27 C28.1@2917.89,1558.91 R32.2@2982.66,1558.91
SRC_U3: R34.1 R38.2 TP13.1 U10.6
SRC_U3_DRL_MCU: pad.7@2765,599 U2.29 U7.1 | length 3555.6
  Top Layer w10: U2.29@478.16,1563.49 478.16,1632.35 490.48,1644.67 ; pad.7@2765,599 2814.79,599 2823.68,607.89 U7.1@2823.68,624.64
  Top Layer w20: 490.48,1644.67 528.98,1683.18 801.34,1683.18 847,1637.52 v1(847,1138)
  Bottom Layer w20: v1(847,1138) 847,893 1240,500 1825,500 1985,340 2447,340 2706,599 pad.7@2765,599
SRC_U3_IN_N: C29.2 R33.2 U7.4 | length 120.6
  Top Layer w10: U7.4@2863.06,682.91 2915.53,682.91 C29.2@2917.89,685.27 R33.2@2982.66,685.27
SRC_U3_IN_P: C29.1 R34.2 U7.3 | length 120.6
  Top Layer w10: U7.3@2863.06,624.64 2915.53,624.64 C29.1@2917.89,622.28 R34.2@2982.66,622.28
Status_U1_ADDA_MCU: J2.5 U2.7 | length 747.7
  Top Layer w10: v1(367.8,1352.77) 367.8,1405.53 382.06,1419.79 U2.7@393.51,1419.79
  Bottom Layer w20: v1(367.8,1352.77) 404.12,1316.46 633.31,1316.46 872.48,1555.63 904.37,1555.63 J2.5@913.3,1564.56
Status_U2_DDA_MCU: J2.7 U2.8 | length 768
  Top Layer w10: v1(351,1286) 351.48,1286.48 351.48,1301.24 393.51,1343.27 U2.8@393.51,1400.1
  Bottom Layer w20: v1(351,1286) 641.35,1286 819.91,1464.56 J2.7@913.3,1464.56
Status_U3_DRL_MCU: J2.9 U2.9 | length 704.7
  Top Layer w10: v1(384.06,1257.8) 384.06,1311.19 419.1,1346.23 U2.9@419.1,1374.51
  Bottom Layer w20: v1(384.06,1257.8) 657.73,1257.8 764.48,1364.56 J2.9@913.3,1364.56
Status_U8_ADDA: J2.6 R14.1 R23.2 TP4.1 U8.3 | length 2603.4
  Top Layer w20: R23.2@2657,2280.5 2681.7,2280.5 2689.31,2288.11 U8.3@2741.2,2288.11
  Top Layer w30: R14.1@1415.11,2215.03 v1(1465.79,2215.03) ; TP4.1@1422.91,1564.69 1490.11,1564.69 1622.62,1697.2 1622.62,2058.2 v1(1465.79,2215.03) ; R23.2@2657,2280.5 1531.26,2280.5 v1(1465.79,2215.03)
  Bottom Layer w30: J2.6@1013.3,1564.56 1422.78,1564.56 TP4.1@1422.91,1564.69
Status_U9_DDA: J2.8 R15.1 R24.2 TP5.1 U9.3 | length 2704.3
  Top Layer w20: R24.2@2663,1351.48 U9.3@2741.2,1351.48
  Top Layer w30: R15.1@1415.11,2105.8 v1(1465.79,2105.8) 1568.43,2003.15 1568.43,1708.33 1501.06,1640.96 1388.13,1640.96 1324.38,1577.21 1324.38,1532.04 TP5.1@1257.04,1464.69 2095.64,1464.69 2208.86,1351.48 R24.2@2663,1351.48
  Bottom Layer w30: J2.8@1013.3,1464.56 1256.9,1464.56 TP5.1@1257.04,1464.69
Status_U10_DRL: J2.10 R16.1 R25.2 TP6.1 U10.1 | length 3507.5
  Top Layer w10: R25.2@2721.62,469.92 2764.28,469.92 2774.67,459.53 U10.1@2818.37,459.53
  Top Layer w30: J2.10@1013.3,1364.56 1182.76,1534.02 1225.21,1534.02 1372.57,1681.38 1479.68,1681.38 1519.64,1721.33 1519.64,1942.72 v1(1465.79,1996.56) R16.1@1415.11,1996.56 ; TP6.1@1422.91,1364.69 2139.05,1364.69 2198.73,1305 2383,1305 2563,1125 2563,570 2663.08,469.92 R25.2@2721.62,469.92
  Bottom Layer w30: J2.10@1013.3,1364.56 1422.78,1364.56 TP6.1@1422.91,1364.69
SWCLK: J1.4 U1.4 U2.24 | length 817.8
  Top Layer w10: U2.24@582.49,1537.9 v1(582.49,1617.49) ; U1.4@635.81,2188.31 635.81,2158.6 646.68,2147.73 v1(678.56,2147.73) ; v1(666.45,1808.44) J1.4@666.45,1880.36
  Bottom Layer w10: v1(582.49,1617.49) 666.45,1701.45 v1(666.45,1808.44) 701.89,1843.87 701.89,2124.4 v1(678.56,2147.73)
SWDIO: J1.2 U1.5 U2.23 | length 890.7
  Top Layer w10: U2.23@582.49,1518.21 603.21,1518.21 613.07,1528.07 v1(613.07,1618.07) ; U1.5@635.81,2208 656.35,2208 v1(671.06,2193.29) ; v1(716.46,1808.44) J1.2@716.46,1880.36
  Bottom Layer w10: v1(613.07,1618.07) 716.46,1721.46 v1(716.46,1808.44) 735.63,1827.62 735.63,2128.72 v1(671.06,2193.29)
VM: C17.2 C18.2 C19.2 C20.2 C21.2 C22.2 C23.2 D10.1 D11.1 D12.1 J8.1 J9.1 J10.1 L1.2 R5.2 TP10.1 TP15.1 TP17.1 TP19.1 U4.2 U4.3 | length 2028.8
  Top Layer w20: R5.2@750.3,1347.75 750.3,1297.7 v1(760,1288)
  Bottom Layer w20: v1(760,1288) 948,1100 948,988 1228.02,707.98 2134.98,707.98 2203,776 v1(2203,916) v1(2203,964)
  other v1: 3509.18,133.09 3652.13,133.09 3738.73,133.09 3836.14,133.09 3931.92,133.09 4028.51,133.09 4125.11,133.09 4221.71,133.09 4318.3,133.09 3510,199 3652.13,199 3836.14,198.68 3931.92,198.68 4029.34,198.68 4125.93,198.68 4222.53,198.68 4319.12,198.68 3836.14,264.28 3931.92,264.28 4028.51,264.28 4221.71,264.28 4318.3,264.28 3836.14,329.87 3931.92,329.87 4028.51,329.87 4125.11,329.87 4221.71,329.87 4318.3,329.87 3509.18,1069.72 3652.13,1069.72 3738.73,1069.72 3836.14,1069.72 3931.92,1069.72 4028.51,1069.72 4125.11,1069.72 4221.71,1069.72 4318.3,1069.72 3836.14,1135.31 3931.92,1135.31 4029.34,1135.31 4125.93,1135.31 4222.53,1135.31 4319.12,1135.31 3510,1135.63 3652.13,1135.63 3836.14,1200.91 3931.92,1200.91 4028.51,1200.91 4221.71,1200.91 4318.3,1200.91 3836.14,1266.5 3931.92,1266.5 4028.51,1266.5 4125.11,1266.5 4221.71,1266.5 4318.3,1266.5 3509.18,2006.35 3652.13,2006.35 3738.73,2006.35 3836.14,2006.35 3931.92,2006.35 4028.51,2006.35 4125.11,2006.35 4221.71,2006.35 4318.3,2006.35 3510,2072.26 3652.13,2072.26 3836.14,2071.95 3931.92,2071.95 4029.34,2071.95 4125.93,2071.95 4222.53,2071.95 4319.12,2071.95 3836.14,2137.54 3931.92,2137.54 4028.51,2137.54 4221.71,2137.54 4318.3,2137.54 3836.14,2203.13 3931.92,2203.13 4028.51,2203.13 4125.11,2203.13 4221.71,2203.13 4318.3,2203.13
  other v3: 2284.09,1902.36 2310.87,1902.36
VM_ADC: R4.2 R5.1 U2.19 | length 180.9
  Top Layer w10: U2.19@582.49,1439.47 593.94,1439.47 613.93,1419.48 R4.2@683.34,1419.47
  Top Layer w20: R5.1@683.37,1347.75 R4.2@683.37,1419.47
VM_IN: C10.2 C11.2 D6.1 J4.1 Q1.1 Q1.2 Q1.3 TP8.1 U3.2 U3.5
pads on no net: FID1.1 FID2.1 FID3.1 H1.0 H2.0 H3.0 H4.0 J1.6 J1.8 Q1.9@1400.17,824.55 Q1.9@1441.22,836.17 Q1.9@1441.22,881.44 Q1.9@1441.22,926.72 Q1.9@1493.58,836.17 Q1.9@1493.58,881.44 Q1.9@1493.58,886.76 Q1.9@1493.58,926.72 Q1.9@1545.94,836.17 Q1.9@1545.94,881.44 Q1.9@1545.94,926.72 Q1.9@1586.98,824.55 SH1-J2.0 SH2-J2.0 SH3-J2.0 SH4-J2.0 SH5-J2.0 SH6-J2.0 SH-J5.0 SH-J6.0 SH-J7.0 U1.2 U2.1 U2.14 U2.16 U2.17 U2.18 U2.25 U2.26 U2.27 U3.3 U3.7 U4.7 U8.4 U9.2 U9.4 U9.5 U10.5

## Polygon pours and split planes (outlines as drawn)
GND on Bottom Layer "NONET_L-01_P-001" (solid, remove dead copper, pour order 8): 4374,2653.49 4252.92,2774.58 132.09,2774.58 25,2667.49 25,145 145,25 4268.01,25 4374,130.99
SRC_U1 on Bottom Layer "NONET_L-01_P-001" (solid, remove dead copper, pour order 4): 2965.51,2359.44 2995.35,2389.27 3026.3,2389.27 3052,2414.97 3052,2488.67 3042.36,2498.31 3002.46,2498.31 2983.06,2517.7 2983.06,2575.54 3002.38,2594.85 3186.15,2594.85 3203.2,2577.8 3203.2,2239.2 3192.31,2228.31 2984.31,2228.31 2965.51,2247.1
VM on Bottom Layer "NONET_L-01_P-001" (solid, remove dead copper, pour order 1): 3529,1275 3005,1275 2839,1106 2501,1106 2373.89,978.89 2373.89,826.11 2425,775 3354,775 3455,876 3646,876 3678.5,843.5 3730,792 3730,527 3470.31,267.31 3470.31,115.69 3561,25 4268.01,25 4374,130.99 4374,2315 4277,2409 3663.4,2409 3425,2170.6 3425,1904.79 3493.79,1836 3652,1836 3713,1775 3713,1459
BUCK_3V3 on Bottom Layer "NONET_L-01_P-001" (solid, remove dead copper, pour order 3): 106,1437 37,1437 27,1427 27,1367 35,1359 232.69,1359 255.89,1382.2 255.89,1473.39 237.28,1492 161,1492
BUCK_3V3 on Bottom Layer "NONET_L-01_P-001" (solid, remove dead copper, pour order 0): 2328.12,1765.39 2394.7,1831.96 2394.7,2028.61 2328.12,2095.19 2328.12,2123.23 2286.13,2165.22 2144.35,2165.22 2129,2149.87 2129,2082 2145,2067 2227,2067 2264.92,2029.08 2264.92,1737.6 2244,1716.67 2244,1672 2264.19,1651.81 2311.76,1651.81 2328.12,1668.04
GND on Top Layer "NONET_L-01_P-001" (solid, remove dead copper, pour order 6): 4374,2653.49 4252.92,2774.58 132.09,2774.58 25,2667.49 25,145 145,25 4268.01,25 4374,130.99

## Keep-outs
Keep-Out Layer:
  lines w10: 0,2800 -0.05,0 4399.95,-0.94
  text ".Layer_Name" at -36.39,-1858.41 h60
